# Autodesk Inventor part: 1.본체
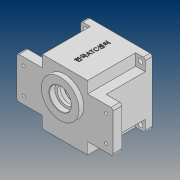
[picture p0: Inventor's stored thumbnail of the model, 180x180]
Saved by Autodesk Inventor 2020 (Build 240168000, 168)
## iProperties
Created: 2020-07
Part Number: 1.본체
Material: 일반
Document SubType Name: Modeling
Designer: PC312-
Density: 1 g/cm^3
Appearance: 기본값
Mass: 324.54 g
Surface Area: 792.48 cm^2
Volume: 324.54 cm^3
Author: PC312-
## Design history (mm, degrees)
sketch "스케치1"
  geometry: L1 (47, 47)-(-47, 47); L2 (-47, 47)-(-47, -47); L3 (-47, -47)-(47, -47); L4 (47, -47)-(47, 47); L5 (47, 47)-(-47, -47); L6 (-47, 47)-(47, -47); 1 further point
  constraints: 12 end point, 2 midpoint, 2 parallel, 1 horizontal, 1 perpendicular
  dimensions: "d0" = 94 distance of L1.start L1.end; "d1" = 94 distance of L3.end L1.start
extrude "돌출1" new body sketch "스케치1" distance "d2" = 10; taper "d3" = 0 deg
sketch "스케치2"
  geometry: L1 (33, 47)-(-33, 47); L2 (-33, 47)-(-33, -47); L3 (-33, -47)-(33, -47); L4 (33, -47)-(33, 47); L5 (33, 47)-(-33, -47); L6 (-33, 47)-(33, -47); L7 (47, 47)-(-47, 47) reference; L8 (47, 30)-(-47, 30); L9 (-47, 30)-(-47, -30); L10 (-47, -30)-(47, -30); L11 (47, -30)-(47, 30); L12 (47, 30)-(-47, -30); L13 (-47, 30)-(47, -30); L14 (47, -47)-(47, 47) reference; 5 further points
  constraints: 24 end point, 4 midpoint, 4 parallel, 2 collinear, 2 horizontal, 2 perpendicular
  dimensions: "d4" = 66 distance of L1.start L1.end; "d5" = 60 distance of L10.end L8.start
extrude "돌출2" join sketch "스케치2" distance "d6" = 57; taper "d7" = 0 deg
sketch "스케치3"
  geometry: L1 (70, 30)-(-70, 30); L2 (-70, 30)-(-70, -30); L3 (-70, -30)-(70, -30); L4 (70, -30)-(70, 30); L5 (70, 30)-(-70, -30); L6 (-70, 30)-(70, -30); L7 (33, 47)-(-33, 47) reference; L8 (-33, 47)-(-33, 30) reference; L9 (33, 30)-(33, 47) reference; L10 (33, -47)-(33, -30) reference; L11 (-33, -47)-(33, -47) reference; L12 (-33, -30)-(-33, -47) reference; 1 further point
  constraints: 12 end point, 2 midpoint, 2 parallel, 1 horizontal, 1 perpendicular
  dimensions: "d8" = 60 distance of L3.end L1.start; "d9" = 140 distance of L1.start L1.end
extrude "돌출3" join sketch "스케치3" distance "d10" = 13; taper "d11" = 0 deg
sketch "스케치4"
  geometry: C1 r 27.5 at (0, 11); 1 further point
  constraints: 1 centre point, 1 vertical alignment
  dimensions: "d12" = 11 distance of point (0, 0) C1.centre; "d13" = 55 diameter of C1
extrude "돌출4" join sketch "스케치4" distance "d14" = 7; taper "d15" = 0 deg
sketch "스케치5"
  geometry: C1 r 43 at (0, 0); 1 further point
  constraints: 1 centre point, 1 coincident
  dimensions: "d16" = 86 diameter of C1
extrude "돌출5" cut sketch "스케치5" distance "d17" = 9; taper "d18" = 0 deg
sketch "스케치10"
  geometry: C1 r 40 at (0, 0); 1 further point
  constraints: 1 centre point, 1 coincident
  dimensions: "d35" = 80 diameter of C1
extrude "돌출8" cut sketch "스케치10" distance "d36" = 71; taper "d37" = 0 deg
sketch "스케치11"
  geometry: A1 r 21 centre (0, 11) between (8.978, -7.984) and (-8.978, -7.984); A2 r 15 centre (0, -20) between (-8.978, -7.984) and (8.978, -7.984); 1 further point
  constraints: 4 point on circle, 2 centre point, 2 vertical alignment
  dimensions: "d38" = 42 diameter of A1; "d39" = 30 diameter of A2; "d40" = 11 distance of point (0, 0) A1.centre; "d41" = 20 distance of point (0, 0) A2.centre
extrude "돌출9" join sketch "스케치11" distance "d42" = 7; taper "d43" = 0 deg
sketch "스케치12"
  geometry: L1 (11, 96.919)-(11, -20.905); L2 (38.5, 87)-(-16.5, 87) reference; L3 (27, 87)-(27, 78.7); L4 (27, 78.7)-(23.5, 78.7); L5 (23.5, 78.7)-(23.5, 74); L6 (23.5, 74)-(28.5, 74); L7 (28.5, 74)-(28.5, 64); L8 (-7.984, 64)-(32, 64) reference; L9 (27, 87)-(11, 87); L10 (28.5, 64)-(11, 64); L11 (11, 87)-(11, 64); 2 further points
  constraints: 18 end point, 4 point on line, 4 vertical, 2 horizontal, 1 midpoint
  dimensions: "d44" = 11 distance from line of point (0, 0) L1; "d45" = 8.3 distance of L3.start L3.end; "d46" = 10 distance of L6.end L7.end; "d47" = 25 diameter of L5 L1; "d48" = 32 diameter of L3 L1; "d49" = 35 diameter of L7 L1
revolve "회전1" sketch "스케치12" stored, may be unused: angle "d50" = 90 deg
sketch "스케치13"
  geometry: L1 (-20, 101.594)-(-20, -10.441); L2 (-35, 64)-(-7.984, 64) reference; L3 (-9, 64)-(-9, 71); L4 (-9, 71)-(-10.5, 71); L5 (-10.5, 71)-(-10.5, 74); L6 (-10.5, 74)-(-20, 74); L7 (-20, 74)-(-20, 64); L8 (-9, 64)-(-20, 64); 1 further point
  constraints: 14 end point, 4 point on line, 3 horizontal, 3 vertical
  dimensions: "d51" = 20 distance from line of point (0, 0) L1; "d52" = 22 diameter of L3 L1; "d53" = 19 diameter of L5 L1; "d54" = 7 distance of L3.start L3.end; "d55" = 3 distance of L4.end L5.end
revolve "회전2" sketch "스케치13" stored, may be unused: angle "d56" = 90 deg
sketch "스케치14"
  geometry: A1 r 36 centre (0, 0) between (-36, 0) and (-35.772, 4.045); A2 r 4 centre (-36, 0) between (-36.19, -3.995) and (-36.19, 3.995); A3 r 3 centre (-36.333, -6.992) between (-35.772, -4.045) and (-39.279, -7.559); A4 r 40 centre (0, 0) between (-39.279, 7.559) and (-39.279, -7.559) reference; A5 r 3 centre (-36.333, 6.992) between (-39.279, 7.559) and (-35.772, 4.045); 1 further point
  constraints: 13 point on circle, 4 centre point, 4 tangent, 1 coincident, 1 horizontal alignment
  dimensions: "d57" = 72 diameter of A1; "d58" = 8 diameter of A2; "d59" = 6 diameter of A3; "d60" = 6 diameter of A5
extrude "돌출10" join sketch "스케치14" distance "d61" = 62; taper "d62" = 0 deg
sketch "스케치15"
  geometry: A1 r 4 centre (-36, 0) between (-36.19, -3.995) and (-36.19, 3.995) reference; 2 further points
  constraints: 1 coincident
hole "구멍1" sketch "스케치15" at (-36, 0) diameter "d63" = 3.242; stored, may be unused: countersink angle "d67" = 90 deg, drill point angle "d69" = 118 deg; dims "d64" = 7, "d65" = 4, "d66" = 2, "d68" = 9
fillet "모깎기1" dims "d70" = 3
sketch "스케치16"
  geometry: L1 (33, -47)-(44, -47) reference; L2 (47, -44)-(47, -30) reference; 2 further points
  dimensions: "d71" = 7 distance from line of L1 point (40, -40); "d72" = 7 distance from line of L2 point (40, -40)
hole "구멍2" sketch "스케치16" at (40, -40) diameter "d73" = 7; stored, may be unused: countersink angle "d77" = 90 deg, drill point angle "d79" = 118 deg; dims "d74" = 7, "d75" = 4, "d76" = 2, "d78" = 9
fillet "모깎기2" dims "d86" = 3
sketch "스케치18"
  geometry: L1 (-67, 30)-(-47, 30) reference; L2 (-70, -27)-(-70, 27) reference; 2 further points
  dimensions: "d87" = 11 distance from line of L1 point (-60, 19); "d88" = 10 distance from line of L2 point (-60, 19)
hole "구멍3" sketch "스케치18" at (-60, 19) diameter "d89" = 4.5; stored, may be unused: countersink angle "d93" = 90 deg, drill point angle "d95" = 118 deg; dims "d90" = 7, "d91" = 10, "d92" = 5, "d94" = 9
chamfer "모따기1" distance "d102" = 0.8; stored, may be unused: second distance "d103" = 2, angle "d104" = 30 deg
chamfer "모따기2" distance "d105" = 1; stored, may be unused: second distance "d106" = 2, angle "d107" = 30 deg
fillet "모깎기3" dims "d108" = 3
node "작업 평면1"
sketch "스케치19"
  geometry: L1 (77, 80)-(-11, 80) reference; 3 further points
  constraints: 1 midpoint, 1 vertical alignment, 1 other
  dimensions: "d110" = 40 distance from line of point (33, 40) L1
feature "엠보싱1" sketch "스케치19" dims "d0" = 94, "d1" = 94, "d5" = 60, "d111" = 0.5, "d112" = 0
node "솔리드1"
mirror "미러1"
pattern_linear "직사각형 패턴1" dims "d82" = 80, "d85" = 80
pattern_linear "직사각형 패턴2" dims "d98" = 38, "d101" = 120
feature "A9D066F2-1C7D-4E18-AEED-F7BC21143FA4" dims "d73" = 7, "d74" = 7, "d75" = 4, "d76" = 2, "d77" = 90 deg, "d78" = 9, "d79" = 118 deg
